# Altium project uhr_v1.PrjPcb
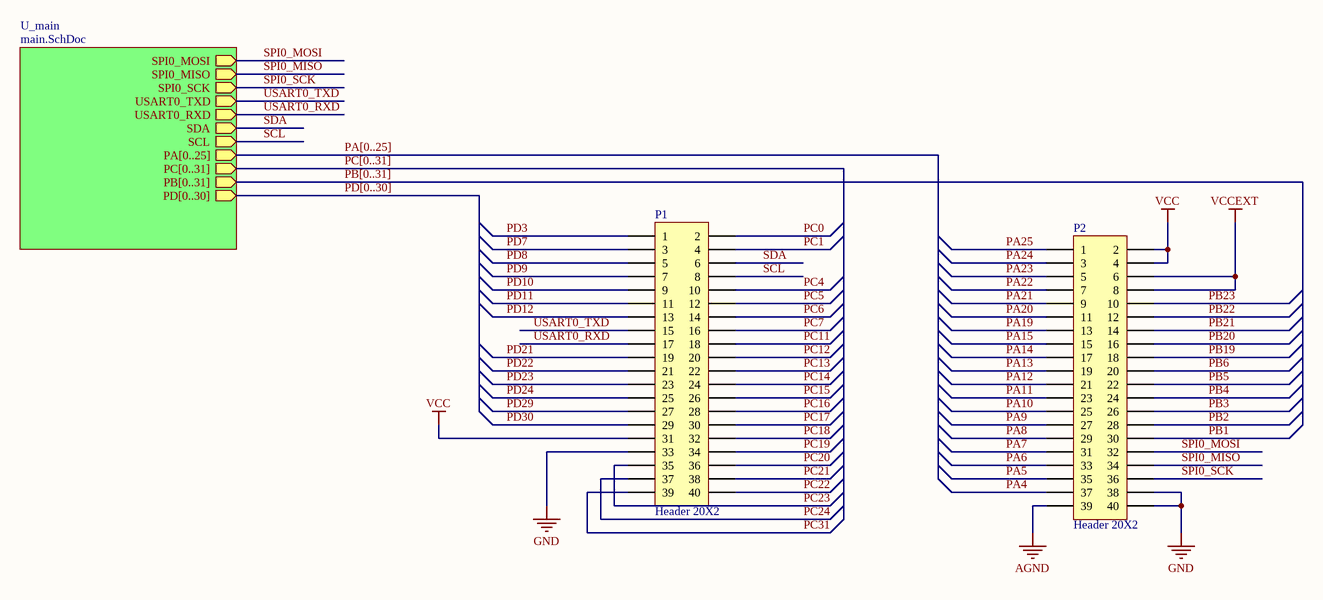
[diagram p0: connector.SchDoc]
2 sheets, 62 parts. Net scope: hierarchical (ports join the sheet entries above them; power ports are global).
Sheets:
  connector.SchDoc
    U_main = main.SchDoc

## Sheet connector.SchDoc
size A3

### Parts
P1  Header 20X2  [HDR2X20_1mm]
P2  Header 20X2  [HDR2X20_1mm]

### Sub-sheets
U_main = main.SchDoc: SPI0_MOSI (out), SPI0_MISO (out), SPI0_SCK (out), USART0_TXD (out), USART0_RXD (out), SDA (out), SCL (out), PA[0..25] (out), PC[0..31] (out), PB[0..31] (out), PD[0..30] (out)

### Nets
AGND: P2.39
GND: P1.33 P2.38 P2.40
VCC: P1.31 P2.2 P2.4
VCCEXT: P2.6 P2.8
PA4: P2.37
PA5: P2.35
PA6: P2.33
PA7: P2.31
PA8: P2.29
PA9: P2.27
PA10: P2.25
PA11: P2.23
PA12: P2.21
PA13: P2.19
PA14: P2.17
PA15: P2.15
PA19: P2.13
PA20: P2.11
PA21: P2.9
PA22: P2.7
PA23: P2.5
PA24: P2.3
PA25: P2.1
PB1: P2.30
PB2: P2.28
PB3: P2.26
PB4: P2.24
PB5: P2.22
PB6: P2.20
PB19: P2.18
PB20: P2.16
PB21: P2.14
PB22: P2.12
PB23: P2.10
PC0: P1.2
PC1: P1.4
PC4: P1.10
PC5: P1.12
PC6: P1.14
PC7: P1.16
PC11: P1.18
PC12: P1.20
PC13: P1.22
PC14: P1.24
PC15: P1.26
PC16: P1.28
PC17: P1.30
PC18: P1.32
PC19: P1.34
PC20: P1.36
PC21: P1.38
PC22: P1.40
PC23: P1.35
PC24: P1.37
PC31: P1.39
PD3: P1.1
PD7: P1.3
PD8: P1.5
PD9: P1.7
PD10: P1.9
PD11: P1.11
PD12: P1.13
PD21: P1.19
PD22: P1.21
PD23: P1.23
PD24: P1.25
PD29: P1.27
PD30: P1.29
SCL: P1.8 ; sheet U_main/SCL
SDA: P1.6 ; sheet U_main/SDA
SPI0_MISO: P2.34 ; sheet U_main/SPI0_MISO
SPI0_MOSI: P2.32 ; sheet U_main/SPI0_MOSI
SPI0_SCK: P2.36 ; sheet U_main/SPI0_SCK
USART0_RXD: P1.17 ; sheet U_main/USART0_RXD
USART0_TXD: P1.15 ; sheet U_main/USART0_TXD

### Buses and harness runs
bus PA[0..25] = sheet U_main/PA[0..25]
bus PB[0..31] = sheet U_main/PB[0..31]
bus PC[0..31] = sheet U_main/PC[0..31]
bus PD[0..30] = sheet U_main/PD[0..30]

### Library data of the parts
P1 P2 = Header 20X2: Header, 20-Pin, Dual row

## Sheet main.SchDoc
size A3
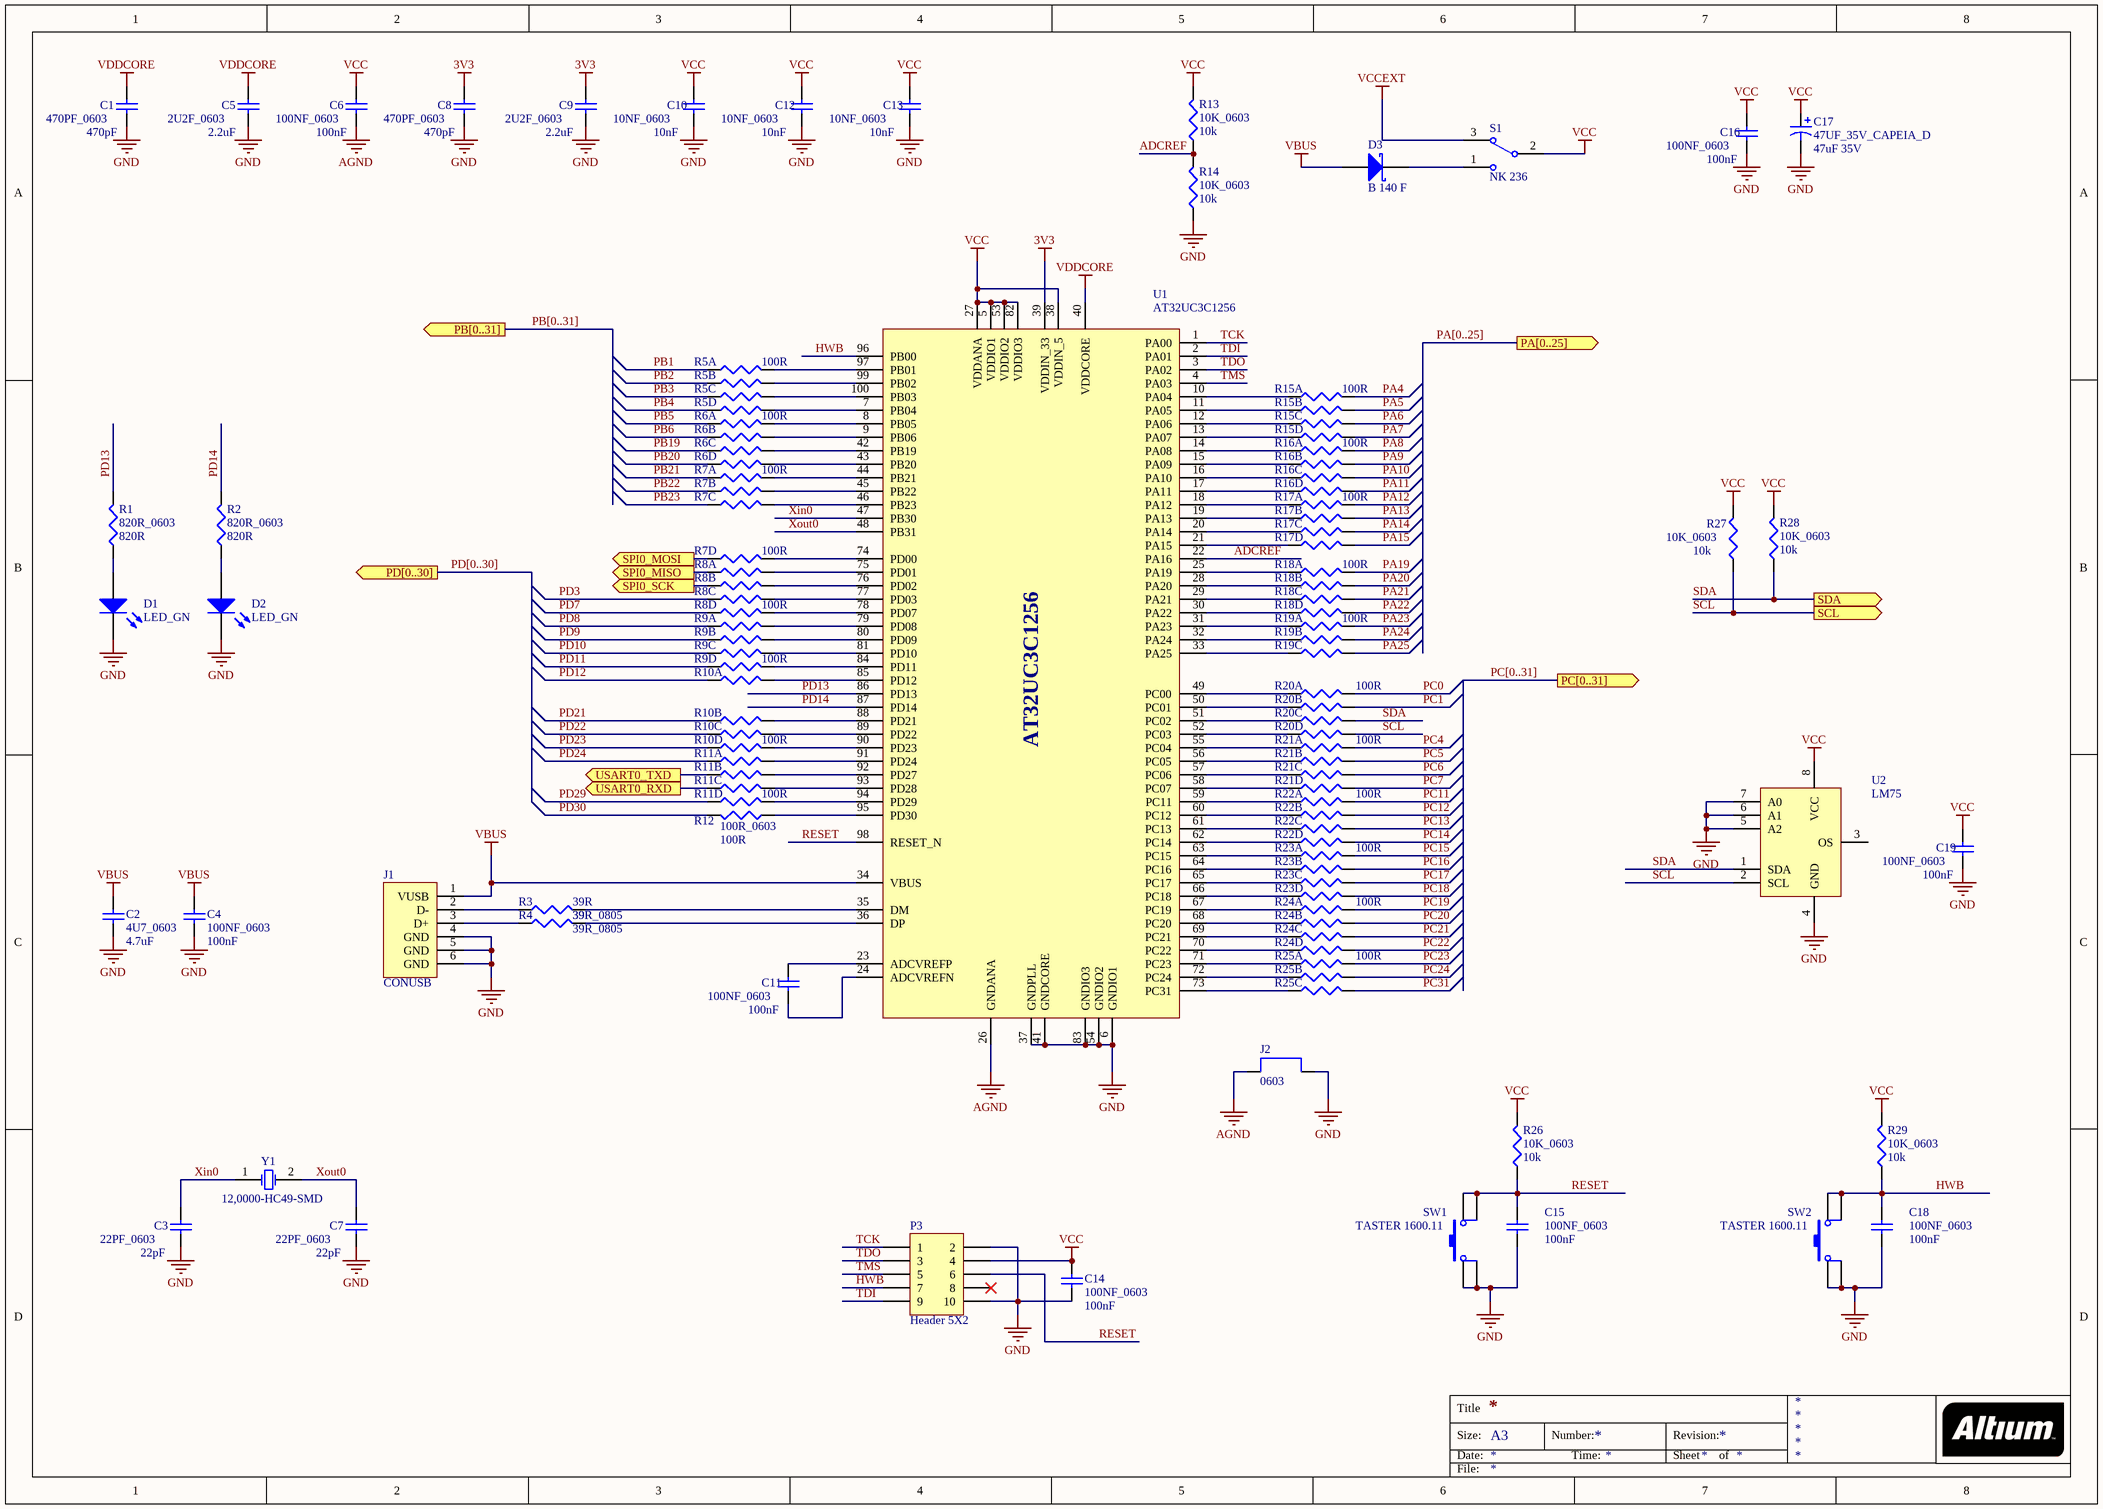
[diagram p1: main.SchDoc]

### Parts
C1  470PF_0603  value 470pF  [C0603]
C2  4U7_0603  value 4.7uF  [C0603]
C3  22PF_0603  value 22pF  [C0603]
C4  100NF_0603  value 100nF  [C0603]
C5  2U2F_0603  value 2.2uF  [C0603]
C6  100NF_0603  value 100nF  [C0603]
C7  22PF_0603  value 22pF  [C0603]
C8  470PF_0603  value 470pF  [C0603]
C9  2U2F_0603  value 2.2uF  [C0603]
C10  10NF_0603  value 10nF  [C0603]
C11  100NF_0603  value 100nF  [C0603]
C12  10NF_0603  value 10nF  [C0603]
C13  10NF_0603  value 10nF  [C0603]
C14  100NF_0603  value 100nF  [C0603]
C15  100NF_0603  value 100nF  [C0603]
C16  100NF_0603  value 100nF  [C0603]
C17  47UF_35V_CAPEIA_D  value 47uF 35V  [CAPAE_D]
C18  100NF_0603  value 100nF  [C0603]
C19  100NF_0603  value 100nF  [C0603]
D1  LED_GN  [LED0603]
D2  LED_GN  [LED0603]
D3  B 140 F  [SMA]
J1  CONUSB  [CON_USBB]
J2  0603  [SolderStrap]
P3  Header 5X2  [HDR2X5]
R1  820R_0603  value 820R  [R0603]
R2  820R_0603  value 820R  [R0603]
R3  39R_0805  value 39R  [R0805]
R4  39R_0805  value 39R  [R0805]
R5  value 100R  [BCN16]  (hidden comment: Res_Array_BCN16)  (parts A,B,C,D of 4)
R6  value 100R  [BCN16]  (hidden comment: Res_Array_BCN16)  (parts A,B,C,D of 4)
R7  value 100R  [BCN16]  (hidden comment: Res_Array_BCN16)  (parts A,B,C,D of 4)
R8  Res_Array_BCN16  [BCN16]  (value not drawn)  (parts A,B,C,D of 4)
R9  Res_Array_BCN16  [BCN16]  (value not drawn)  (parts A,B,C,D of 4)
R10  Res_Array_BCN16  [BCN16]  (value not drawn)  (parts A,B,C,D of 4)
R11  Res_Array_BCN16  [BCN16]  (value not drawn)  (parts A,B,C,D of 4)
R12  100R_0603  value 100R  [R0603]
R13  10K_0603  value 10k  [R0603]
R14  10K_0603  value 10k  [R0603]
R15  value 100R  [BCN16]  (hidden comment: Res_Array_BCN16)  (parts A,B,C,D of 4)
R16  value 100R  [BCN16]  (hidden comment: Res_Array_BCN16)  (parts A,B,C,D of 4)
R17  value 100R  [BCN16]  (hidden comment: Res_Array_BCN16)  (parts A,B,C,D of 4)
R18  value 100R  [BCN16]  (hidden comment: Res_Array_BCN16)  (parts A,B,C,D of 4)
R19  value 100R  [BCN16]  (hidden comment: Res_Array_BCN16)  (parts A,B,C of 4)
R20  100R  [BCN16]  (parts A,B,C,D of 4)
R21  100R  [BCN16]  (parts A,B,C,D of 4)
R22  100R  [BCN16]  (parts A,B,C,D of 4)
R23  100R  [BCN16]  (parts A,B,C,D of 4)
R24  100R  [BCN16]  (parts A,B,C,D of 4)
R25  100R  [BCN16]  (parts A,B,C of 4)
R26  10K_0603  value 10k  [R0603]
R27  10K_0603  value 10k  [R0603]
R28  10K_0603  value 10k  [R0603]
R29  10K_0603  value 10k  [R0603]
S1  NK 236  [NK236]
SW1  TASTER 1600.11  [PUSHBUTTON_SMD]
SW2  TASTER 1600.11  [PUSHBUTTON_SMD]
U1  AT32UC3C1256  [TQFP100]
U2  LM75  [SOIC-8]
Y1  12,0000-HC49-SMD  [HC49-SMD]

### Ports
PA[0..25] (out), PB[0..31] (out), PC[0..31] (out), PD[0..30] (out), SCL (out), SDA (out), SPI0_MISO (out), SPI0_MOSI (out), SPI0_SCK (out), USART0_RXD (out), USART0_TXD (out)

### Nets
3V3: C8.2 C9.2 U1.39(VDDIN_33)
AGND: C6.1 J2.1 U1.26(GNDANA)
GND: C1.1 C2.1 C3.1 C4.1 C5.1 C7.1 C8.1 C9.1 C10.1 C12.1 C13.1 C14.1 C15.1 C16.1 C17.2 C18.1 C19.1 D1.2(K) D2.2(K) J1.4(GND) J1.5(GND) J1.6(GND) J2.2 P3.2 P3.10 R14.1 SW1.1 SW1.2 SW2.1 SW2.2 U1.6(GNDIO1) U1.37(GNDPLL) U1.41(GNDCORE) U1.54(GNDIO2) U1.83(GNDIO3) U2.4(GND) U2.5(A2) U2.6(A1) U2.7(A0)
VBUS: C2.2 C4.2 D3.1(A) J1.1(VUSB) U1.34(VBUS)
VCC: C6.2 C10.2 C12.2 C13.2 C14.2 C16.2 C17.1 C19.2 P3.4 R13.2 R26.2 R27.2 R28.2 R29.2 S1.2 U1.5(VDDIO1) U1.27(VDDANA) U1.38(VDDIN_5) U1.53(VDDIO2) U1.82(VDDIO3) U2.8(VCC)
VCCEXT: S1.3
VDDCORE: C1.2 C5.2 U1.40(VDDCORE)
ADCREF: R13.1 R14.2 U1.22(PA16)
HWB: C18.2 P3.7 R29.1 SW2.3 SW2.4 U1.96(PB00)
PA4: R15.8
PA5: R15.7
PA6: R15.6
PA7: R15.5
PA8: R16.8
PA9: R16.7
PA10: R16.6
PA11: R16.5
PA12: R17.8
PA13: R17.7
PA14: R17.6
PA15: R17.5
PA19: R18.8
PA20: R18.7
PA21: R18.6
PA22: R18.5
PA23: R19.8
PA24: R19.7
PA25: R19.6
PB1: R5.1
PB2: R5.2
PB3: R5.3
PB4: R5.4
PB5: R6.1
PB6: R6.2
PB19: R6.3
PB20: R6.4
PB21: R7.1
PB22: R7.2
PB23: R7.3
PC0: R20.8
PC1: R20.7
PC4: R21.8
PC5: R21.7
PC6: R21.6
PC7: R21.5
PC11: R22.8
PC12: R22.7
PC13: R22.6
PC14: R22.5
PC15: R23.8
PC16: R23.7
PC17: R23.6
PC18: R23.5
PC19: R24.8
PC20: R24.7
PC21: R24.6
PC22: R24.5
PC23: R25.8
PC24: R25.7
PC31: R25.6
PD3: R8.3
PD7: R8.4
PD8: R9.1
PD9: R9.2
PD10: R9.3
PD11: R9.4
PD12: R10.1
PD13: R1.2 U1.86(PD13)
PD14: R2.2 U1.87(PD14)
PD21: R10.2
PD22: R10.3
PD23: R10.4
PD24: R11.1
PD29: R11.4
PD30: R12.2
RESET: C15.2 P3.6 R26.1 SW1.3 SW1.4 U1.98(RESET_N)
SCL: R20.5 R27.1 U2.2(SCL) ; port SCL
SDA: R20.6 R28.1 U2.1(SDA) ; port SDA
SPI0_MISO: R8.1 ; port SPI0_MISO
SPI0_MOSI: R7.4 ; port SPI0_MOSI
SPI0_SCK: R8.2 ; port SPI0_SCK
TCK: P3.1 U1.1(PA00)
TDI: P3.9 U1.2(PA01)
TDO: P3.3 U1.3(PA02)
TMS: P3.5 U1.4(PA03)
USART0_RXD: R11.3 ; port USART0_RXD
USART0_TXD: R11.2 ; port USART0_TXD
Xin0: C3.2 U1.47(PB30) Y1.1(OSC1)
Xout0: C7.2 U1.48(PB31) Y1.2(OSC2)
NetC11_1: C11.1 U1.24(ADCVREFN)
NetC11_2: C11.2 U1.23(ADCVREFP)
NetD1_1: D1.1(A) R1.1
NetD2_1: D2.1(A) R2.1
NetD3_2: D3.2(K) S1.1
NetJ1_2: J1.2(D-) R3.1
NetJ1_3: J1.3(D+) R4.1
NetR3_2: R3.2 U1.35(DM)
NetR4_2: R4.2 U1.36(DP)
NetR5_5: R5.5 U1.7(PB04)
NetR5_6: R5.6 U1.100(PB03)
NetR5_7: R5.7 U1.99(PB02)
NetR5_8: R5.8 U1.97(PB01)
NetR6_5: R6.5 U1.43(PB20)
NetR6_6: R6.6 U1.42(PB19)
NetR6_7: R6.7 U1.9(PB06)
NetR6_8: R6.8 U1.8(PB05)
NetR7_5: R7.5 U1.74(PD00)
NetR7_6: R7.6 U1.46(PB23)
NetR7_7: R7.7 U1.45(PB22)
NetR7_8: R7.8 U1.44(PB21)
NetR8_5: R8.5 U1.78(PD07)
NetR8_6: R8.6 U1.77(PD03)
NetR8_7: R8.7 U1.76(PD02)
NetR8_8: R8.8 U1.75(PD01)
NetR9_5: R9.5 U1.84(PD11)
NetR9_6: R9.6 U1.81(PD10)
NetR9_7: R9.7 U1.80(PD09)
NetR9_8: R9.8 U1.79(PD08)
NetR10_5: R10.5 U1.90(PD23)
NetR10_6: R10.6 U1.89(PD22)
NetR10_7: R10.7 U1.88(PD21)
NetR10_8: R10.8 U1.85(PD12)
NetR11_5: R11.5 U1.94(PD29)
NetR11_6: R11.6 U1.93(PD28)
NetR11_7: R11.7 U1.92(PD27)
NetR11_8: R11.8 U1.91(PD24)
NetR12_1: R12.1 U1.95(PD30)
NetR15_1: R15.1 U1.10(PA04)
NetR15_2: R15.2 U1.11(PA05)
NetR15_3: R15.3 U1.12(PA06)
NetR15_4: R15.4 U1.13(PA07)
NetR16_1: R16.1 U1.14(PA08)
NetR16_2: R16.2 U1.15(PA09)
NetR16_3: R16.3 U1.16(PA10)
NetR16_4: R16.4 U1.17(PA11)
NetR17_1: R17.1 U1.18(PA12)
NetR17_2: R17.2 U1.19(PA13)
NetR17_3: R17.3 U1.20(PA14)
NetR17_4: R17.4 U1.21(PA15)
NetR18_1: R18.1 U1.25(PA19)
NetR18_2: R18.2 U1.28(PA20)
NetR18_3: R18.3 U1.29(PA21)
NetR18_4: R18.4 U1.30(PA22)
NetR19_1: R19.1 U1.31(PA23)
NetR19_2: R19.2 U1.32(PA24)
NetR19_3: R19.3 U1.33(PA25)
NetR20_1: R20.1 U1.49(PC00)
NetR20_2: R20.2 U1.50(PC01)
NetR20_3: R20.3 U1.51(PC02)
NetR20_4: R20.4 U1.52(PC03)
NetR21_1: R21.1 U1.55(PC04)
NetR21_2: R21.2 U1.56(PC05)
NetR21_3: R21.3 U1.57(PC06)
NetR21_4: R21.4 U1.58(PC07)
NetR22_1: R22.1 U1.59(PC11)
NetR22_2: R22.2 U1.60(PC12)
NetR22_3: R22.3 U1.61(PC13)
NetR22_4: R22.4 U1.62(PC14)
NetR23_1: R23.1 U1.63(PC15)
NetR23_2: R23.2 U1.64(PC16)
NetR23_3: R23.3 U1.65(PC17)
NetR23_4: R23.4 U1.66(PC18)
NetR24_1: R24.1 U1.67(PC19)
NetR24_2: R24.2 U1.68(PC20)
NetR24_3: R24.3 U1.69(PC21)
NetR24_4: R24.4 U1.70(PC22)
NetR25_1: R25.1 U1.71(PC23)
NetR25_2: R25.2 U1.72(PC24)
NetR25_3: R25.3 U1.73(PC31)

Not connected (* = marked no-connect by the designer): P3 8*; U2 3(OS)

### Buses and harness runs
bus PA[0..25] = port PA[0..25]
bus PB[0..31] = port PB[0..31]
bus PC[0..31] = port PC[0..31]
bus PD[0..30] = port PD[0..30]

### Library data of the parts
C1-C16 C18 C19 = Cap Semi: Capacitor (Semiconductor SIM Model)
C17 = Cap Pol1: Polarized Capacitor (Radial)
D1 D2 = LED0: Typical INFRARED GaAs LED
D3 = D Schottky: Schottky Diode; pin to pad: 1>2 2>1
J1 = CON_USBB
J2 = SolderStrap: Resistor; Value: 1K
P3 = Header 5X2: Header, 5-Pin, Dual row
R1-R4 R12-R14 R26-R29 = Res3: Resistor
R5-R11 R15-R25 = Res_Array_BCN16: Resistor
S1 = SW-SPDT: SPDT Subminiature Toggle Switch, Right Angle Mounting, Vertical Actuation
SW1 SW2 = PushButtonSMD
Y1 = XTAL: Crystal Oscillator

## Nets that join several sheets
AGND: connector (P2.39), main (C6.1 J2.1 U1.26)
GND: connector (P1.33 P2.38 P2.40), main (39 pins)
VCC: connector (P1.31 P2.2 P2.4), main (21 pins)
VCCEXT: connector (P2.6 P2.8), main (S1.3)
PA4: connector (P2.37), main (R15.8)
PA5: connector (P2.35), main (R15.7)
PA6: connector (P2.33), main (R15.6)
PA7: connector (P2.31), main (R15.5)
PA8: connector (P2.29), main (R16.8)
PA9: connector (P2.27), main (R16.7)
PA10: connector (P2.25), main (R16.6)
PA11: connector (P2.23), main (R16.5)
PA12: connector (P2.21), main (R17.8)
PA13: connector (P2.19), main (R17.7)
PA14: connector (P2.17), main (R17.6)
PA15: connector (P2.15), main (R17.5)
PA19: connector (P2.13), main (R18.8)
PA20: connector (P2.11), main (R18.7)
PA21: connector (P2.9), main (R18.6)
PA22: connector (P2.7), main (R18.5)
PA23: connector (P2.5), main (R19.8)
PA24: connector (P2.3), main (R19.7)
PA25: connector (P2.1), main (R19.6)
PB1: connector (P2.30), main (R5.1)
PB2: connector (P2.28), main (R5.2)
PB3: connector (P2.26), main (R5.3)
PB4: connector (P2.24), main (R5.4)
PB5: connector (P2.22), main (R6.1)
PB6: connector (P2.20), main (R6.2)
PB19: connector (P2.18), main (R6.3)
PB20: connector (P2.16), main (R6.4)
PB21: connector (P2.14), main (R7.1)
PB22: connector (P2.12), main (R7.2)
PB23: connector (P2.10), main (R7.3)
PC0: connector (P1.2), main (R20.8)
PC1: connector (P1.4), main (R20.7)
PC4: connector (P1.10), main (R21.8)
PC5: connector (P1.12), main (R21.7)
PC6: connector (P1.14), main (R21.6)
PC7: connector (P1.16), main (R21.5)
PC11: connector (P1.18), main (R22.8)
PC12: connector (P1.20), main (R22.7)
PC13: connector (P1.22), main (R22.6)
PC14: connector (P1.24), main (R22.5)
PC15: connector (P1.26), main (R23.8)
PC16: connector (P1.28), main (R23.7)
PC17: connector (P1.30), main (R23.6)
PC18: connector (P1.32), main (R23.5)
PC19: connector (P1.34), main (R24.8)
PC20: connector (P1.36), main (R24.7)
PC21: connector (P1.38), main (R24.6)
PC22: connector (P1.40), main (R24.5)
PC23: connector (P1.35), main (R25.8)
PC24: connector (P1.37), main (R25.7)
PC31: connector (P1.39), main (R25.6)
PD3: connector (P1.1), main (R8.3)
PD7: connector (P1.3), main (R8.4)
PD8: connector (P1.5), main (R9.1)
PD9: connector (P1.7), main (R9.2)
PD10: connector (P1.9), main (R9.3)
PD11: connector (P1.11), main (R9.4)
PD12: connector (P1.13), main (R10.1)
PD21: connector (P1.19), main (R10.2)
PD22: connector (P1.21), main (R10.3)
PD23: connector (P1.23), main (R10.4)
PD24: connector (P1.25), main (R11.1)
PD29: connector (P1.27), main (R11.4)
PD30: connector (P1.29), main (R12.2)
SCL: connector (P1.8), main (R20.5 R27.1 U2.2)
SDA: connector (P1.6), main (R20.6 R28.1 U2.1)
SPI0_MISO: connector (P2.34), main (R8.1)
SPI0_MOSI: connector (P2.32), main (R7.4)
SPI0_SCK: connector (P2.36), main (R8.2)
USART0_RXD: connector (P1.17), main (R11.3)
USART0_TXD: connector (P1.15), main (R11.2)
